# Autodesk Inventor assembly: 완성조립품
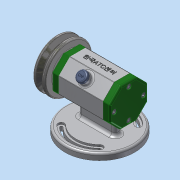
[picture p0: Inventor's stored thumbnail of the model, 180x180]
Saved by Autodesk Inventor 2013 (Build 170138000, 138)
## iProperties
Created: 2017-06
Part Number: 완성조립품
Document SubType Name: Assembly
Designer: Administrator
Author: Administrator
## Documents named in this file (14)
- C:\Users\Administrator\Desktop\470608V1010\완성조립품.iam
- C:\Users\Administrator\Desktop\470608V1010\본체.ipt
- C:\Users\Administrator\Desktop\470608V1010\베어링 15 x 32 x 9.ipt
- C:\Users\Administrator\Desktop\470608V1010\뒤커버.ipt
- C:\Users\Administrator\Desktop\470608V1010\앞커버.ipt
- C:\Users\Administrator\Desktop\470608V1010\오일 실 15 25 7.ipt
- C:\Users\Administrator\Desktop\470608V1010\볼트 M4 x 12.ipt
- C:\Users\Administrator\Desktop\470608V1010\축.ipt
- C:\Users\Administrator\Desktop\470608V1010\키 3 x 3 x 12.ipt
- C:\Users\Administrator\Desktop\470608V1010\V벨트풀리.ipt
- C:\Users\Administrator\Desktop\470608V1010\와셔 8x17.ipt
- C:\Users\Administrator\Desktop\470608V1010\스프링와셔 8.ipt
- C:\Users\Administrator\Desktop\470608V1010\너트 M 8.ipt
- C:\Users\Administrator\Desktop\470608V1010\고무캡.ipt
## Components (2 placed, 2 different names)
1. V벨트풀리:1
2. 고무캡:1
